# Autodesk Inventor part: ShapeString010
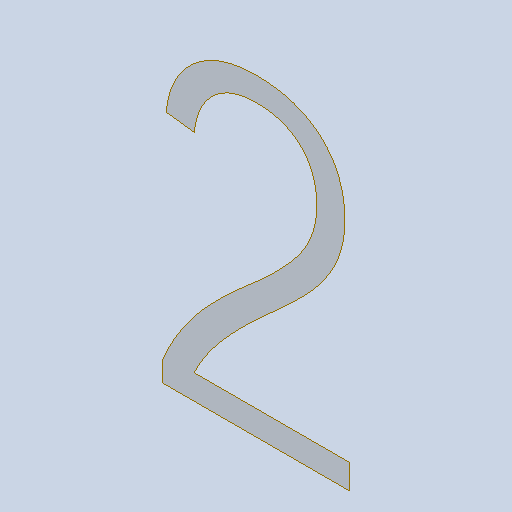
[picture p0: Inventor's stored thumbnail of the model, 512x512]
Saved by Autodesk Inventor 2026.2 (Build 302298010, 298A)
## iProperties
Created: 2026-10
Part Number: ShapeString010
Material: Générique
Document SubType Name: Modeling
Designer: mel
Density: 1 g/cm^3
Appearance: Par défaut
Author: mel
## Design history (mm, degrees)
feature "Composite1"
body "Srf1"
